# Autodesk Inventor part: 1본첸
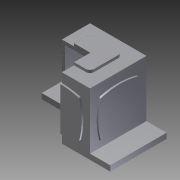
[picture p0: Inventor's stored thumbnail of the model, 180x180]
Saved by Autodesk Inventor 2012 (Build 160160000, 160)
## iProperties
Created: 2012-07
Part Number: 1본첸
Material: Default
Document SubType Name: Modeling
Designer: JANG KYOUNG-IL
Density: 1 g/cm^3
Author: JANG KYOUNG-IL
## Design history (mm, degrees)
sketch "스케치1"
  geometry: L1 (-90, 52.5)-(90, 52.5); L2 (90, 52.5)-(90, -52.5); L3 (90, -52.5)-(-90, -52.5); L4 (-90, -52.5)-(-90, 52.5); 3 further points
  constraints: 8 end point, 2 midpoint, 2 parallel, 1 horizontal, 1 horizontal alignment, 1 perpendicular, 1 vertical alignment
  dimensions: "d0" = 180 distance of L2.end L3.end; "d1" = 105 distance of L3.end L1.start
extrude "돌출1" new body sketch "스케치1" distance "d2" = 10; taper "d3" = 0 deg
sketch "스케치2"
  geometry: L1 (-52.5, 52.5)-(52.5, 52.5); L2 (52.5, 52.5)-(52.5, -52.5); L3 (52.5, -52.5)-(-52.5, -52.5); L4 (-52.5, -52.5)-(-52.5, 52.5); 3 further points
  constraints: 8 end point, 2 midpoint, 2 parallel, 2 perpendicular, 1 horizontal, 1 horizontal alignment, 1 vertical alignment
  dimensions: "d4" = 105 distance of L1.end L1.start
extrude "돌출2" new body sketch "스케치2" distance "d5" = 115; taper "d6" = 0 deg
feature "쉘1" dims "d7" = 10, "d8" = 6
feature "결합1"
  node "솔리드1"
sketch "스케치3"
  geometry: L1 (-30, 30)-(30, 30); L2 (30, 30)-(30, -30); L3 (30, -30)-(-30, -30); L4 (-30, -30)-(-30, 30); 3 further points
  constraints: 8 end point, 2 midpoint, 2 parallel, 2 perpendicular, 1 horizontal, 1 horizontal alignment, 1 vertical alignment
  dimensions: "d9" = 60 distance of L1.end L1.start
extrude "돌출3" join sketch "스케치3" distance "d10" = 5; taper "d11" = 0 deg
fillet "모깎기1" dims "d25" = 8
sketch "스케치4"
  geometry: L1 (-82.502, 17.498)-(-12.498, 17.498); L2 (-12.498, 17.498)-(-12.498, 87.502); L3 (-12.498, 87.502)-(-82.502, 87.502); L4 (-82.502, 87.502)-(-82.502, 17.498); A1 r 125.055 centre (37.555, 52.5) between (-82.502, 87.502) and (-82.502, 17.498); A2 r 125.055 centre (-132.555, 52.5) between (-12.498, 17.498) and (-12.498, 87.502); A3 r 125.055 centre (-47.5, 137.555) between (-82.502, 17.498) and (-12.498, 17.498); A4 r 125.055 centre (-47.5, -32.555) between (-12.498, 87.502) and (-82.502, 87.502); 2 further points
  constraints: 8 end point, 8 point on circle, 4 centre point, 2 equal radius, 2 parallel, 2 perpendicular, 1 horizontal, 1 horizontal alignment, 1 midpoint
  dimensions: "d12" = 99 distance of L3.end L1.end; "d13" = 80 dimension on A2 A1; "d18" = 80 dimension on A4 A3; "d19" = 57.5 horizontal distance of A4.centre point (10, 52.5)
extrude "돌출4" join sketch "스케치4" distance "d20" = 3; taper "d21" = 0 deg
fillet "모깎기2" dims "d26" = 3
pattern_circular "원형 패턴1" dims angle "d23" = 180 deg
node "솔리드2"
